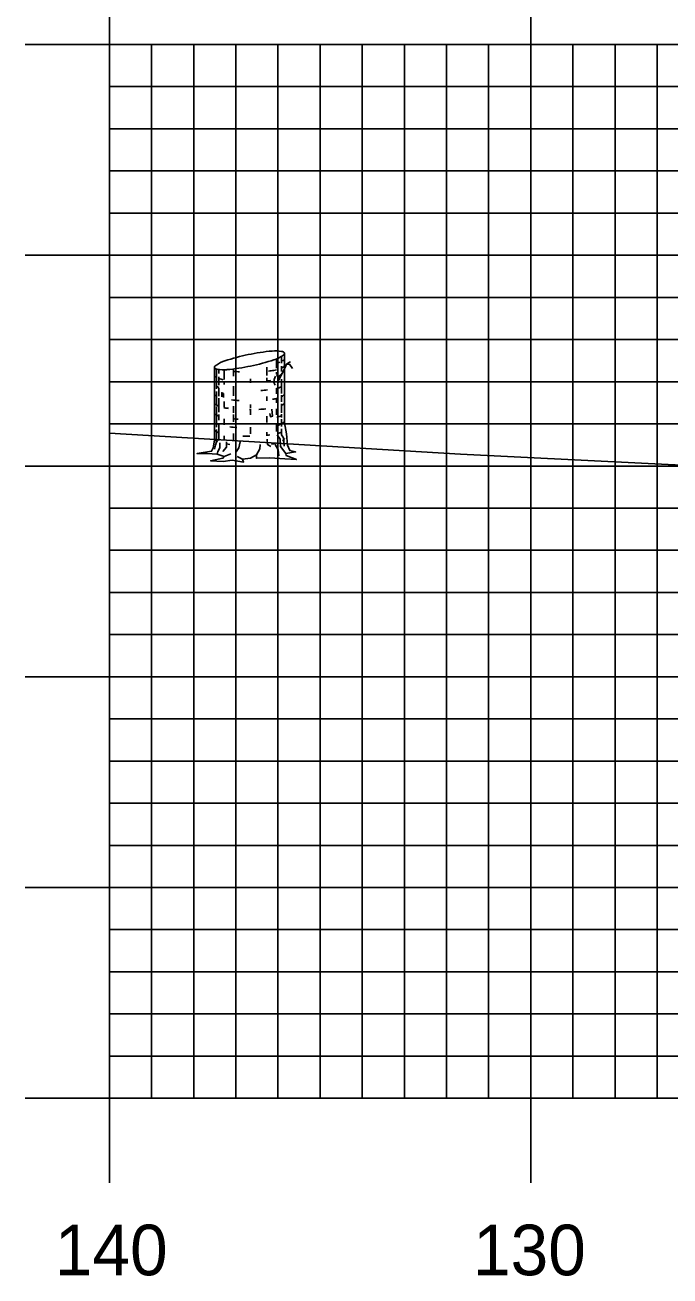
# Model space of a CAD drawing. Extents: x 1772022 to 1772366, y 442591 to 442811.
# Drawn here: x 1772046.09 to 1772061.4, y 442649.45 to 442679.13 of the extents above; entities that cross this region are included whole.
import ezdxf

# ---------------------------------------------------------------- set-up
doc = ezdxf.new("R2010")
doc.units = 0
for name, color, linetype in [('H_V ANNOTATION', 7, 'Continuous'), ('M_Trees_Conifer_Pay', 7, 'Continuous'), ('MAJOR', 7, 'Continuous'), ('MINOR', 7, 'Continuous'), ('S_Roadway_Centerline', 7, 'Continuous')]:
    doc.layers.add(name, color=color, linetype=linetype)

msp = doc.modelspace()

# ---------------------------------------------------------------- linework, layer by layer
at = {"layer": 'M_Trees_Conifer_Pay'}
for p, q in [((1772052.177, 442671.267), (1772052.177, 442671.105)), ((1772052.249, 442669.692), (1772052.249, 442671.339)), ((1772050.585, 442669.282), (1772050.585, 442671.004)), ((1772050.632, 442670.967), (1772050.632, 442670.496)), ((1772051.035, 442670.968), (1772051.035, 442670.8)), ((1772051.831, 442671.01), (1772051.831, 442670.811)), ((1772052.06, 442671.206), (1772052.06, 442670.983)), ((1772052.177, 442671.037), (1772052.177, 442670.909)), ((1772050.69, 442670.956), (1772050.69, 442670.858)), ((1772050.69, 442670.784), (1772050.69, 442670.58)), ((1772050.815, 442670.948), (1772050.815, 442670.715)), ((1772050.815, 442670.675), (1772050.815, 442670.601)), ((1772051.441, 442670.736), (1772051.441, 442670.641)), ((1772051.831, 442670.753), (1772051.831, 442670.664)), ((1772052.06, 442670.895), (1772052.06, 442670.847)), ((1772052.117, 442670.711), (1772052.065, 442670.652)), ((1772052.177, 442670.722), (1772052.177, 442670.386)), ((1772050.632, 442670.431), (1772050.632, 442670.123)), ((1772050.69, 442670.522), (1772050.69, 442670.322)), ((1772051.035, 442670.563), (1772051.035, 442670.326)), ((1772052.06, 442670.512), (1772052.06, 442670.38)), ((1772050.632, 442670.076), (1772050.632, 442669.584)), ((1772050.69, 442670.275), (1772050.69, 442669.939)), ((1772050.815, 442670.197), (1772050.815, 442670.059)), ((1772051.035, 442670.082), (1772051.035, 442669.929)), ((1772051.441, 442670.123), (1772051.441, 442670.049)), ((1772051.831, 442670.316), (1772051.831, 442670.211)), ((1772052.06, 442670.269), (1772052.06, 442670.16)), ((1772052.177, 442670.349), (1772052.177, 442670.187)), ((1772052.177, 442670.139), (1772052.177, 442669.923)), ((1772050.69, 442669.886), (1772050.69, 442669.75)), ((1772050.815, 442669.787), (1772050.815, 442669.645)), ((1772051.035, 442669.886), (1772051.035, 442669.713)), ((1772051.441, 442670.024), (1772051.441, 442669.876)), ((1772051.831, 442669.845), (1772051.831, 442669.698)), ((1772052.06, 442670.024), (1772052.06, 442669.882)), ((1772052.177, 442669.892), (1772052.177, 442669.818)), ((1772052.177, 442669.777), (1772052.177, 442669.604)), ((1772050.632, 442669.53), (1772050.632, 442669.282)), ((1772050.69, 442669.651), (1772050.69, 442669.273)), ((1772051.441, 442669.584), (1772051.441, 442669.431)), ((1772052.06, 442669.655), (1772052.06, 442669.482)), ((1772050.815, 442669.383), (1772050.815, 442669.289)), ((1772051.035, 442669.435), (1772051.035, 442669.282)), ((1772051.831, 442669.466), (1772051.831, 442669.378)), ((1772050.815, 442668.889), (1772050.978, 442668.953)), ((1772051.252, 442668.825), (1772051.127, 442668.889))]:
    msp.add_line(p, q, dxfattribs=at)
for points in [[(1772052.065, 442670.837), (1772052.102, 442670.763), (1772052.149, 442670.82), (1772052.207, 442670.889), (1772052.3, 442671.082), (1772052.364, 442671.129), (1772052.395, 442671.136)], [(1772052.08, 442670.584), (1772052.117, 442670.711), (1772052.18, 442670.827), (1772052.211, 442670.895), (1772052.28, 442671.041)], [(1772052.294, 442671.07), (1772052.37, 442671.078), (1772052.442, 442670.979)], [(1772052.032, 442670.8), (1772052.001, 442670.715), (1772051.997, 442670.648), (1772052.028, 442670.584)], [(1772050.764, 442670.31), (1772050.758, 442670.405), (1772050.801, 442670.382), (1772050.801, 442670.288)], [(1772051.903, 442669.911), (1772051.915, 442669.834), (1772051.962, 442669.845), (1772051.95, 442670.011)], [(1772052.249, 442669.692), (1772052.3, 442669.431), (1772052.316, 442669.157), (1772052.374, 442669.032), (1772052.51, 442669.001), (1772052.279, 442668.963), (1772052.279, 442668.963), (1772052.285, 442668.916), (1772052.533, 442668.822), (1772052.258, 442668.838), (1772051.903, 442668.858), (1772051.581, 442668.848), (1772051.588, 442668.931), (1772051.439, 442668.848), (1772051.252, 442668.825), (1772051.277, 442668.757), (1772051.009, 442668.801), (1772050.789, 442668.774), (1772050.496, 442668.791), (1772050.785, 442668.848), (1772050.815, 442668.889), (1772050.653, 442668.947), (1772050.416, 442668.958), (1772050.175, 442668.958), (1772050.517, 442669.015), (1772050.558, 442669.095), (1772050.585, 442669.282)], [(1772052.174, 442669.55), (1772052.18, 442669.404), (1772052.228, 442669.336), (1772052.238, 442669.137)], [(1772050.632, 442669.235), (1772050.611, 442669.157), (1772050.591, 442669.063)], [(1772050.71, 442669.215), (1772050.716, 442669.099), (1772050.663, 442669.011), (1772050.653, 442668.947)], [(1772050.873, 442669.242), (1772050.873, 442669.11), (1772050.785, 442669.011)], [(1772051.1, 442669.001), (1772051.167, 442669.095), (1772051.194, 442669.235)], [(1772051.838, 442669.299), (1772051.849, 442669.173), (1772051.923, 442669.13)], [(1772052.075, 442669.404), (1772052.149, 442669.299), (1772052.154, 442669.126), (1772052.279, 442668.963)], [(1772051.588, 442668.931), (1772051.662, 442669.072), (1772051.672, 442669.173)], [(1772052.117, 442668.91), (1772052.102, 442669.048), (1772052.028, 442669.177)]]:
    msp.add_lwpolyline(points, dxfattribs=at)
for centre, radius, start, end in [((1772052.44, 442666.237), 5.179, 101.7194, 108.0594), ((1772052.44, 442666.237), 5.179, 95.3794, 101.7194), ((1772052.03, 442670.595), 0.802, 79.2194, 95.3794), ((1772051.75, 442671.945), 0.802, 288.0594, 304.2194), ((1772052.133, 442671.136), 0.251, 71.0501, 79.2194), ((1772052.06, 442671.49), 0.251, 304.2194, 312.3887), ((1772052.188, 442671.296), 0.0817, 56.7194, 71.0501), ((1772052.174, 442671.365), 0.0817, 312.3887, 326.7194), ((1772052.204, 442671.32), 0.0527, 46.923, 56.7194), ((1772052.218, 442671.335), 0.0314, 34.2194, 46.923), ((1772052.198, 442671.349), 0.0527, 326.7194, 336.5158), ((1772052.223, 442671.338), 0.0264, 23.4074, 34.2194), ((1772052.217, 442671.341), 0.0314, 336.5158, 349.2194), ((1772052.226, 442671.34), 0.0226, 11.7194, 23.4074), ((1772052.226, 442671.34), 0.0226, 0.0315, 11.7194), ((1772052.222, 442671.34), 0.0264, 349.2194, 0.0315), ((1772050.616, 442671.003), 0.0314, 156.5158, 169.2194), ((1772050.611, 442671.004), 0.0264, 169.2194, 180.0315), ((1772050.607, 442671.004), 0.0226, 180.0315, 191.7194), ((1772050.607, 442671.004), 0.0226, 191.7194, 203.4074), ((1772050.611, 442671.005), 0.0264, 203.4074, 214.2194), ((1772050.635, 442670.994), 0.0527, 146.7194, 156.5158), ((1772050.615, 442671.008), 0.0314, 214.2194, 226.923), ((1772050.66, 442670.979), 0.0817, 132.3887, 146.7194), ((1772050.629, 442671.024), 0.0527, 226.923, 236.7194), ((1772050.645, 442671.048), 0.0817, 236.7194, 251.0501), ((1772050.774, 442670.854), 0.251, 124.2194, 132.3887), ((1772050.7, 442671.208), 0.251, 251.0501, 259.2194), ((1772051.083, 442670.398), 0.802, 108.0594, 124.2194), ((1772050.803, 442671.749), 0.802, 259.2194, 275.3794), ((1772050.393, 442676.107), 5.179, 275.3794, 281.7194), ((1772050.393, 442676.107), 5.179, 281.7194, 288.0594), ((1772051.918, 442671.653), 0.571, 284.4317, 292.4132), ((1772051.918, 442671.499), 0.571, 297.0237, 300), ((1772052.117, 442671.308), 0.172, 300, 311.2506), ((1772052.117, 442671.153), 0.172, 300, 311.2506), ((1772052.189, 442671.225), 0.0624, 311.2506, 330), ((1772052.189, 442671.071), 0.0624, 311.2506, 330), ((1772052.205, 442671.216), 0.0441, 330, 343.9485), ((1772052.205, 442671.062), 0.0441, 330, 343.9485), ((1772052.215, 442671.213), 0.0334, 343.9485, 354.2151), ((1772052.215, 442671.059), 0.0334, 343.9485, 354.2151), ((1772050.617, 442670.826), 0.0334, 163.9485, 180), ((1772050.617, 442670.826), 0.0334, 180, 196.0515), ((1772050.627, 442670.829), 0.0441, 196.0515, 210), ((1772050.643, 442670.838), 0.0624, 210, 228.7494), ((1772050.715, 442670.921), 0.172, 228.7494, 240), ((1772050.914, 442671.266), 0.571, 240, 240.3367), ((1772050.914, 442671.266), 0.571, 246.8597, 257.9846), ((1772051.417, 442675.016), 4.124, 264.6955, 266.7331), ((1772051.415, 442674.783), 4.124, 268.0751, 270), ((1772051.415, 442674.783), 4.124, 275.7849, 277.0558), ((1772051.417, 442675.016), 4.124, 276.238, 278.1032), ((1772051.918, 442671.499), 0.571, 278.1032, 284.3667), ((1772050.617, 442670.379), 0.0334, 163.9485, 180), ((1772050.617, 442670.379), 0.0334, 180, 196.0515), ((1772050.627, 442670.382), 0.0441, 196.0515, 210), ((1772050.916, 442671.055), 0.571, 240, 247.0587), ((1772051.415, 442674.783), 4.124, 270, 270.3581), ((1772051.417, 442674.572), 4.124, 273.7052, 275.9504), ((1772051.917, 442671.055), 0.571, 284.4493, 297.0429), ((1772052.204, 442670.382), 0.0441, 330, 343.9485), ((1772052.214, 442670.379), 0.0334, 343.9485, 354.2151), ((1772052.215, 442670.615), 0.0334, 343.9485, 354.2151), ((1772050.617, 442670.169), 0.0334, 163.9485, 180), ((1772050.617, 442670.169), 0.0334, 180, 196.0515), ((1772050.627, 442670.172), 0.0441, 196.0515, 210), ((1772050.643, 442670.391), 0.0624, 210, 228.7494), ((1772050.643, 442670.181), 0.0624, 210, 228.7494), ((1772050.715, 442670.474), 0.172, 228.7494, 240), ((1772050.715, 442670.264), 0.172, 228.7494, 240), ((1772050.914, 442670.819), 0.571, 240, 240.3367), ((1772050.914, 442670.609), 0.571, 240, 246.8597), ((1772051.415, 442674.336), 4.124, 264.081, 266.6676), ((1772051.415, 442674.336), 4.124, 277.6125, 278.1032), ((1772051.916, 442670.819), 0.571, 278.1032, 286.9296), ((1772051.916, 442670.819), 0.571, 297.1896, 300), ((1772051.916, 442670.609), 0.571, 297.1896, 300), ((1772052.115, 442670.474), 0.172, 300, 311.2506), ((1772052.115, 442670.264), 0.172, 300, 311.2506), ((1772052.188, 442670.391), 0.0624, 311.2506, 330), ((1772052.188, 442670.181), 0.0624, 311.2506, 330), ((1772052.204, 442670.172), 0.0441, 330, 343.9485), ((1772052.214, 442670.169), 0.0334, 343.9485, 354.2151), ((1772050.617, 442669.932), 0.0334, 163.9485, 180), ((1772050.617, 442669.932), 0.0334, 180, 196.0515), ((1772050.627, 442669.935), 0.0441, 196.0515, 210), ((1772050.643, 442669.944), 0.0624, 210, 228.7494), ((1772050.715, 442670.027), 0.172, 228.7494, 240), ((1772050.914, 442670.372), 0.571, 240, 246.8597), ((1772050.914, 442670.609), 0.571, 259.2707, 261.8968), ((1772051.415, 442674.126), 4.124, 261.8968, 263.1474), ((1772051.415, 442673.89), 4.124, 264.716, 266.3193), ((1772051.415, 442674.126), 4.124, 270, 270.3581), ((1772051.415, 442674.126), 4.124, 273.1493, 275.4569), ((1772051.916, 442670.372), 0.571, 285.3983, 297.1896), ((1772050.617, 442669.735), 0.0334, 163.9485, 180), ((1772050.617, 442669.539), 0.0334, 163.9485, 180), ((1772050.617, 442669.539), 0.0334, 180, 196.0515), ((1772050.627, 442669.542), 0.0441, 196.0515, 210), ((1772050.643, 442669.551), 0.0624, 210, 228.7494), ((1772050.715, 442669.634), 0.172, 228.7494, 240), ((1772050.904, 442670.18), 0.571, 241.2369, 248.0268), ((1772050.914, 442669.979), 0.571, 240, 246.8597), ((1772051.415, 442673.692), 4.124, 263.4991, 265.8397), ((1772051.916, 442670.174), 0.571, 289.2907, 300), ((1772052.115, 442669.829), 0.172, 300, 311.2506), ((1772052.188, 442669.747), 0.0624, 311.2506, 330), ((1772052.204, 442669.738), 0.0441, 330, 343.9485), ((1772052.214, 442669.735), 0.0334, 343.9485, 354.2151), ((1772050.617, 442669.319), 0.0334, 163.9485, 180), ((1772050.617, 442669.319), 0.0334, 180, 196.0515), ((1772050.627, 442669.322), 0.0441, 196.0515, 210), ((1772050.643, 442669.331), 0.0624, 210, 228.7494), ((1772050.715, 442669.413), 0.172, 228.7494, 240), ((1772050.914, 442669.758), 0.571, 240, 244.5314), ((1772051.415, 442673.276), 4.124, 262.4438, 263.512), ((1772051.415, 442673.496), 4.124, 267.8117, 270), ((1772051.415, 442673.496), 4.124, 270, 270.1328), ((1772051.415, 442673.496), 4.124, 275.7849, 276.7896), ((1772051.415, 442673.276), 4.124, 277.3684, 278.1032), ((1772051.916, 442669.758), 0.571, 278.1032, 281.637), ((1772051.916, 442669.979), 0.571, 288.5067, 297.2721), ((1772052.115, 442669.413), 0.172, 300, 311.2506), ((1772052.188, 442669.331), 0.0624, 311.2506, 330), ((1772052.204, 442669.322), 0.0441, 330, 343.9485), ((1772052.214, 442669.319), 0.0334, 343.9485, 354.2151)]:
    msp.add_arc(centre, radius, start, end, dxfattribs=at)
at = {"layer": 'MAJOR'}
for p, q in [((1772048.094, 442680.669), (1772048.094, 442678.665)), ((1772058.094, 442680.669), (1772058.094, 442678.665)), ((1772046.09, 442678.665), (1772048.094, 442678.665)), ((1772048.094, 442678.665), (1772328.094, 442678.665)), ((1772048.094, 442653.665), (1772048.094, 442678.665)), ((1772048.094, 442653.665), (1772048.094, 442678.665)), ((1772048.094, 442678.665), (1772328.094, 442678.665)), ((1772058.094, 442653.665), (1772058.094, 442678.665)), ((1772046.09, 442673.665), (1772048.094, 442673.665)), ((1772048.094, 442673.665), (1772328.094, 442673.665)), ((1772046.09, 442668.665), (1772048.094, 442668.665)), ((1772048.094, 442668.665), (1772328.094, 442668.665)), ((1772046.09, 442663.665), (1772048.094, 442663.665)), ((1772048.094, 442663.665), (1772328.094, 442663.665)), ((1772046.09, 442658.665), (1772048.094, 442658.665)), ((1772048.094, 442658.665), (1772328.094, 442658.665)), ((1772046.09, 442653.665), (1772048.094, 442653.665)), ((1772048.094, 442653.665), (1772328.094, 442653.665)), ((1772048.094, 442653.665), (1772328.094, 442653.665)), ((1772048.094, 442651.661), (1772048.094, 442653.665)), ((1772058.094, 442651.661), (1772058.094, 442653.665))]:
    msp.add_line(p, q, dxfattribs=at)
at = {"layer": 'MINOR'}
for p, q in [((1772049.094, 442653.665), (1772049.094, 442678.665)), ((1772050.094, 442653.665), (1772050.094, 442678.665)), ((1772051.094, 442653.665), (1772051.094, 442678.665)), ((1772052.094, 442653.665), (1772052.094, 442678.665)), ((1772053.094, 442653.665), (1772053.094, 442678.665)), ((1772054.094, 442653.665), (1772054.094, 442678.665)), ((1772055.094, 442653.665), (1772055.094, 442678.665)), ((1772056.094, 442653.665), (1772056.094, 442678.665)), ((1772057.094, 442653.665), (1772057.094, 442678.665)), ((1772059.094, 442653.665), (1772059.094, 442678.665)), ((1772060.094, 442653.665), (1772060.094, 442678.665)), ((1772061.094, 442653.665), (1772061.094, 442678.665)), ((1772048.094, 442677.665), (1772328.094, 442677.665)), ((1772048.094, 442677.665), (1772050.098, 442677.665)), ((1772048.094, 442676.665), (1772328.094, 442676.665)), ((1772048.094, 442676.665), (1772050.098, 442676.665)), ((1772048.094, 442675.665), (1772328.094, 442675.665)), ((1772048.094, 442675.665), (1772050.098, 442675.665)), ((1772048.094, 442674.665), (1772328.094, 442674.665)), ((1772048.094, 442674.665), (1772050.098, 442674.665)), ((1772048.094, 442672.665), (1772328.094, 442672.665)), ((1772048.094, 442672.665), (1772050.098, 442672.665)), ((1772048.094, 442671.665), (1772328.094, 442671.665)), ((1772048.094, 442671.665), (1772050.098, 442671.665)), ((1772048.094, 442670.665), (1772328.094, 442670.665)), ((1772048.094, 442670.665), (1772050.098, 442670.665)), ((1772048.094, 442669.665), (1772328.094, 442669.665)), ((1772048.094, 442669.665), (1772050.098, 442669.665)), ((1772048.094, 442667.665), (1772328.094, 442667.665)), ((1772048.094, 442667.665), (1772050.098, 442667.665)), ((1772048.094, 442666.665), (1772328.094, 442666.665)), ((1772048.094, 442666.665), (1772050.098, 442666.665)), ((1772048.094, 442665.665), (1772328.094, 442665.665)), ((1772048.094, 442665.665), (1772050.098, 442665.665)), ((1772048.094, 442664.665), (1772328.094, 442664.665)), ((1772048.094, 442664.665), (1772050.098, 442664.665)), ((1772048.094, 442662.665), (1772328.094, 442662.665)), ((1772048.094, 442662.665), (1772050.098, 442662.665)), ((1772048.094, 442661.665), (1772328.094, 442661.665)), ((1772048.094, 442661.665), (1772050.098, 442661.665)), ((1772048.094, 442660.665), (1772328.094, 442660.665)), ((1772048.094, 442660.665), (1772050.098, 442660.665)), ((1772048.094, 442659.665), (1772328.094, 442659.665)), ((1772048.094, 442659.665), (1772050.098, 442659.665)), ((1772048.094, 442657.665), (1772328.094, 442657.665)), ((1772048.094, 442657.665), (1772050.098, 442657.665)), ((1772048.094, 442656.665), (1772328.094, 442656.665)), ((1772048.094, 442656.665), (1772050.098, 442656.665)), ((1772048.094, 442655.665), (1772328.094, 442655.665)), ((1772048.094, 442655.665), (1772050.098, 442655.665)), ((1772048.094, 442654.665), (1772328.094, 442654.665)), ((1772048.094, 442654.665), (1772050.098, 442654.665))]:
    msp.add_line(p, q, dxfattribs=at)
at = {"layer": 'S_Roadway_Centerline'}
msp.add_lwpolyline([(1772048.094, 442669.441), (1772056.429, 442668.948), (1772066.454, 442668.448), (1772068.508, 442668.251), (1772071.595, 442668.049), (1772079.781, 442667.654), (1772085.527, 442667.353), (1772090.854, 442667.407), (1772097.533, 442666.923), (1772106.7, 442666.846), (1772114.442, 442666.922), (1772125.595, 442666.322), (1772126.179, 442666.296), (1772126.588, 442666.301), (1772137.909, 442665.932)], dxfattribs=at)

# ---------------------------------------------------------------- texts
at = {"layer": 'H_V ANNOTATION'}
for s, p in [('140', (1772046.798, 442649.465)), ('130', (1772056.723, 442649.465))]:
    msp.add_text(s, height=1.2, dxfattribs=at).set_placement(p)
at = {"layer": 'MAJOR'}
msp.add_text('-', height=0.012, dxfattribs=at).set_placement((1772048.085, 442653.665))

doc.saveas('drawing.dxf')
